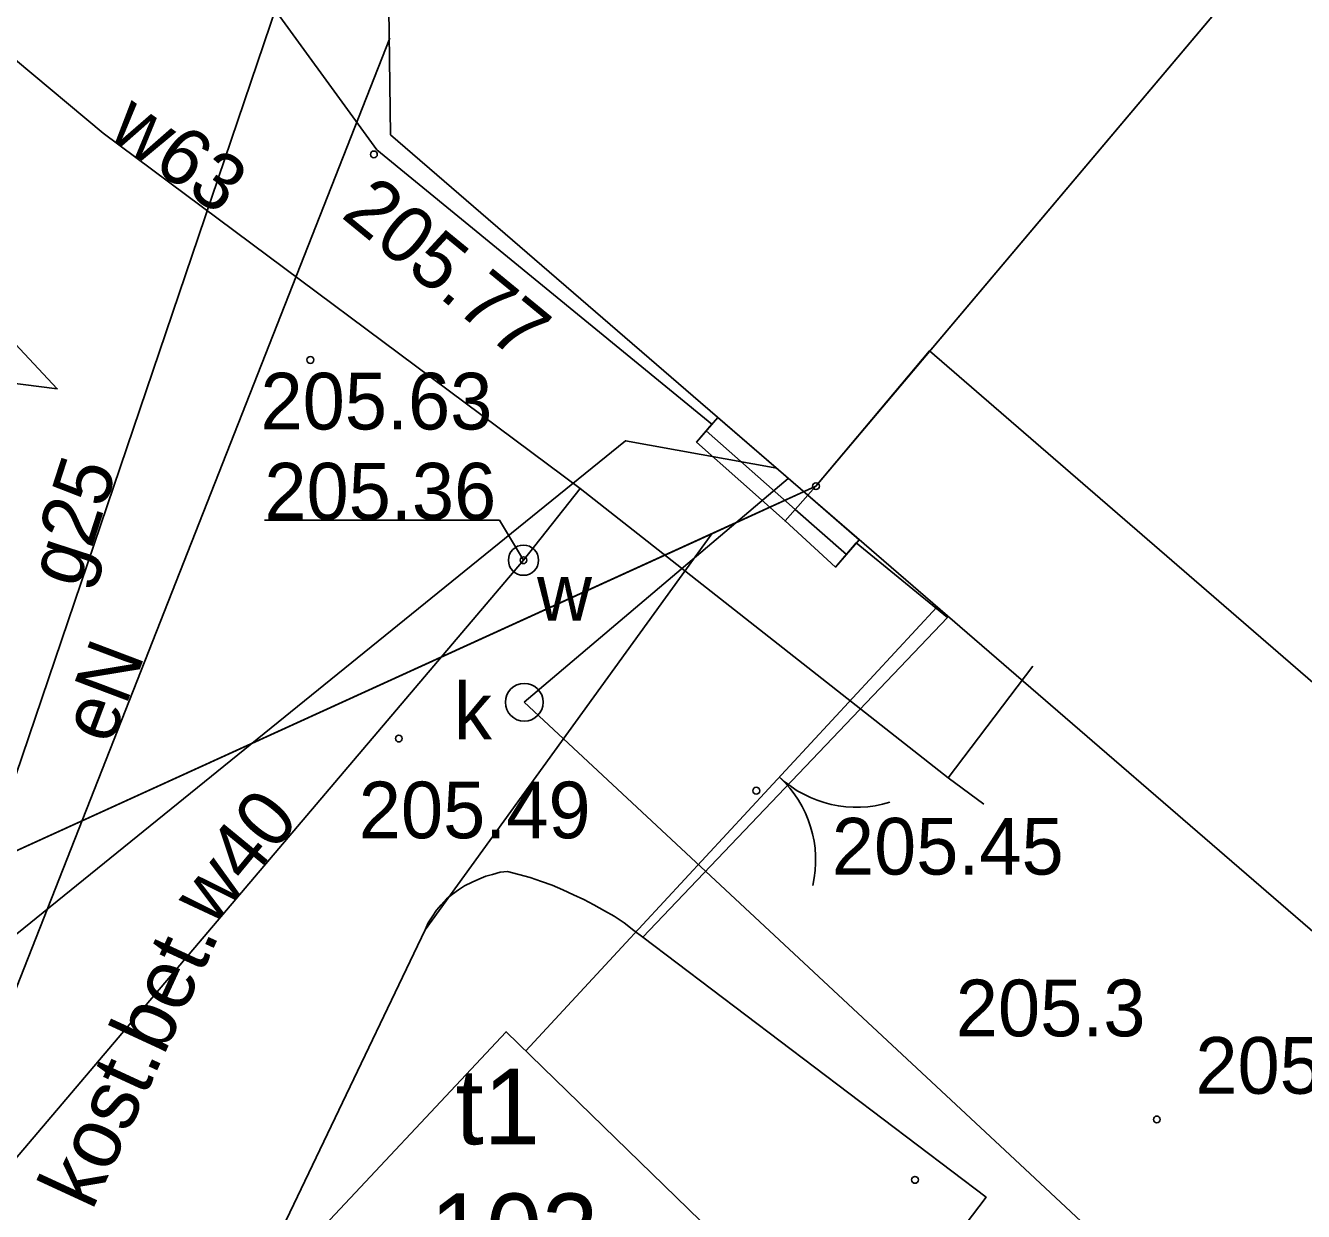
# Model space of a CAD drawing. Extents: x 6512606 to 6513006, y 6022524 to 6022728.
# Drawn here: x 6512766.96 to 6512783.87, y 6022649.64 to 6022665.33 of the extents above; entities that cross this region are included whole.
import ezdxf

# ---------------------------------------------------------------- set-up
doc = ezdxf.new("R2010")
doc.units = 0
for name, color, linetype in [('203-punkt graniczny', 7, 'Continuous'), ('217-kontur klasyfikacyjny', 7, 'Continuous'), ('218-kontur użytku gruntowego', 7, 'Continuous'), ('219-działka ewidencyjna', 7, 'Continuous'), ('312-budynek ewidencyjny', 7, 'Continuous'), ('312-oznaczenie budynku ewidencyjnego', 7, 'Continuous'), ('312-oznaczenie budynku ewidencyjnego-Atr117', 7, 'Continuous'), ('320-blok - kondygnacja nadziemna', 7, 'Continuous'), ('352-schody', 7, 'Continuous'), ('4', 7, 'Continuous'), ('433-Chodnik', 7, 'Continuous'), ('brama', 7, 'Continuous'), ('chodnik', 7, 'Continuous'), ('chodnik (powierzchnia)', 7, 'Continuous'), ('Default', 7, 'Continuous'), ('obszar utwardzony', 7, 'Continuous'), ('ogrodzenie trwałe', 7, 'Continuous'), ('pikieta naturalna', 7, 'Continuous'), ('pikieta naturalna-Atr2', 7, 'Continuous'), ('pikieta sztuczna', 7, 'Continuous'), ('pikieta sztuczna-Atr2', 7, 'Continuous'), ('przewód elektroenergetyczny (linia)', 7, 'Continuous'), ('przewód elektroenergetyczny (linia)-Atr1', 7, 'Continuous'), ('przewód gazowy (linia)', 7, 'Continuous'), ('przewód gazowy (linia)-Atr1', 7, 'Continuous'), ('przewód kanalizacyjny (linia)', 7, 'Continuous'), ('przewód wodociągowy (linia)', 7, 'Continuous'), ('przewód wodociągowy (linia)-Atr1', 7, 'Continuous'), ('punkt o określonej wysokości (sieć wodociągowa)', 7, 'Continuous'), ('punkt o określonej wysokości (sieć wodociągowa)-Atr2', 7, 'Continuous'), ('właz okrągły - siec kanalizacyjna (punkt)', 7, 'Continuous'), ('właz okrągły - siec kanalizacyjna (punkt)-Atr17', 7, 'Continuous'), ('zasuwa - siec wodociągowa (punkt)', 7, 'Continuous'), ('zasuwa - siec wodociągowa (punkt)-Atr17', 7, 'Continuous')]:
    doc.layers.add(name, color=color, linetype=linetype)

# ---------------------------------------------------------------- blocks, each defined once
blk = doc.blocks.new('203')
at = {"layer": 'Default'}
blk.add_circle((0, 0), 0.45, dxfattribs=at)
blk = doc.blocks.new('US22')
at = {"layer": 'Default'}
blk.add_circle((0, 0), 2.5, dxfattribs=at)
blk = doc.blocks.new('US25')
at = {"layer": 'Default'}
blk.add_circle((0, 0), 2, dxfattribs=at)
blk = doc.blocks.new('PW01')
at = {"layer": 'Default'}
blk.add_circle((0, 0), 0.45, dxfattribs=at)
blk = doc.blocks.new('OK02')
at = {"layer": 'Default'}
for centre, start, end in [((-15, 0), 0, 60), ((15, 0), 120, 180)]:
    blk.add_arc(centre, 15, start, end, dxfattribs=at)

msp = doc.modelspace()

# ---------------------------------------------------------------- linework, layer by layer
at = {"layer": '217-kontur klasyfikacyjny'}
for points in [[(6512786.09, 6022669.52), (6512777.42, 6022659.24)], [(6512777.42, 6022659.24), (6512776.04, 6022658.61)], [(6512776.04, 6022658.61), (6512772.25, 6022653.37)], [(6512772.25, 6022653.37), (6512764.49, 6022637.17)]]:
    msp.add_lwpolyline(points, dxfattribs=at)
at = {"layer": '218-kontur użytku gruntowego'}
for points in [[(6512786.09, 6022669.52), (6512777.42, 6022659.24)], [(6512777.42, 6022659.24), (6512786.09, 6022669.52)], [(6512762.17, 6022652.29), (6512777.42, 6022659.24)], [(6512777.42, 6022659.24), (6512776.04, 6022658.61)], [(6512776.04, 6022658.61), (6512762.17, 6022652.29)], [(6512776.04, 6022658.61), (6512772.25, 6022653.37)], [(6512772.25, 6022653.37), (6512776.04, 6022658.61)], [(6512772.25, 6022653.37), (6512764.49, 6022637.17)], [(6512764.49, 6022637.17), (6512772.25, 6022653.37)]]:
    msp.add_lwpolyline(points, dxfattribs=at)
at = {"layer": '219-działka ewidencyjna'}
for points in [[(6512777.42, 6022659.24), (6512790.49, 6022674.74)], [(6512777.42, 6022659.24), (6512762.17, 6022652.29)]]:
    msp.add_lwpolyline(points, dxfattribs=at)
at = {"layer": '312-budynek ewidencyjny'}
for points in [[(6512779.23, 6022661.39), (6512786.09, 6022669.52)], [(6512786.09, 6022669.52), (6512779.23, 6022661.39)], [(6512771.79, 6022663.89), (6512771.75, 6022666.89)], [(6512777.31, 6022659.12), (6512771.79, 6022663.89)], [(6512779.23, 6022661.39), (6512777.42, 6022659.24), (6512777.31, 6022659.12)], [(6512779.23, 6022661.39), (6512777.42, 6022659.24)], [(6512785.97, 6022651.64), (6512777.31, 6022659.12)]]:
    msp.add_lwpolyline(points, dxfattribs=at)
msp.add_lwpolyline([(6512770.59, 6022649.11), (6512773.32, 6022652.02), (6512775.89, 6022649.52), (6512773.2, 6022646.66)], close=True, dxfattribs=at)
at = {"layer": '320-blok - kondygnacja nadziemna'}
msp.add_lwpolyline([(6512787.51, 6022651.8), (6512788.38, 6022652.85), (6512778.92, 6022661.03), (6512777.42, 6022659.24), (6512777.31, 6022659.12), (6512785.97, 6022651.64)], close=True, dxfattribs=at)
at = {"layer": '352-schody'}
for points in [[(6512776.12, 6022660.15), (6512777.31, 6022659.12), (6512777.01, 6022658.78), (6512775.84, 6022659.82)], [(6512776.12, 6022660.15), (6512777.31, 6022659.12), (6512777.01, 6022658.78), (6512775.84, 6022659.82)], [(6512777.31, 6022659.12), (6512777.99, 6022658.53), (6512777.68, 6022658.17), (6512777.01, 6022658.78)], [(6512777.31, 6022659.12), (6512777.99, 6022658.53), (6512777.68, 6022658.17), (6512777.01, 6022658.78)]]:
    msp.add_lwpolyline(points, close=True, dxfattribs=at)
for points in [[(6512775.968, 6022659.971), (6512777.145, 6022658.933)], [(6512777.145, 6022658.933), (6512777.822, 6022658.335)]]:
    msp.add_lwpolyline(points, dxfattribs=at)
at = {"layer": '4'}
for points in [[(6512777.42, 6022659.24), (6512790.49, 6022674.74)], [(6512777.42, 6022659.24), (6512762.17, 6022652.29)]]:
    msp.add_lwpolyline(points, dxfattribs=at)
at = {"layer": 'brama'}
msp.add_lwpolyline([(6512779.02, 6022657.64), (6512774.85, 6022653.14)], dxfattribs=at)
at = {"layer": 'chodnik'}
msp.add_lwpolyline([(6512764.49, 6022637.17), (6512772.25, 6022653.37), (6512772.29, 6022653.46), (6512772.34, 6022653.54), (6512772.4, 6022653.63), (6512772.46, 6022653.7), (6512772.53, 6022653.78), (6512772.61, 6022653.84), (6512772.69, 6022653.9), (6512772.77, 6022653.95), (6512772.87, 6022654), (6512772.96, 6022654.04), (6512773.05, 6022654.08), (6512773.14, 6022654.1), (6512773.24, 6022654.13), (6512773.34, 6022654.14), (6512773.49, 6022654.1), (6512773.64, 6022654.06), (6512773.79, 6022654.01), (6512773.93, 6022653.96), (6512774.07, 6022653.9), (6512774.21, 6022653.83), (6512774.35, 6022653.77), (6512774.48, 6022653.7), (6512774.62, 6022653.62), (6512774.75, 6022653.55), (6512774.88, 6022653.46), (6512775.01, 6022653.36), (6512775.13, 6022653.27), (6512779.16, 6022657.5), (6512777.95, 6022658.49), (6512777.68, 6022658.17), (6512777.01, 6022658.78), (6512775.84, 6022659.82), (6512776.04, 6022660.06), (6512771.61, 6022663.69), (6512768.44, 6022668.05)], dxfattribs=at)
at = {"layer": 'chodnik (powierzchnia)'}
msp.add_lwpolyline([(6512762.98, 6022661.09), (6512767.38, 6022660.53), (6512765.47, 6022662.57), (6512765.23, 6022662.76), (6512764.98, 6022662.95), (6512764.72, 6022663.13), (6512764.45, 6022663.28), (6512764.18, 6022663.44), (6512763.9, 6022663.57), (6512763.61, 6022663.7), (6512763.32, 6022663.81), (6512763.02, 6022663.91), (6512762.72, 6022664), (6512762.41, 6022664.06), (6512762.11, 6022664.13), (6512761.8, 6022664.17), (6512761.49, 6022664.19), (6512761.68, 6022661.21)], close=True, dxfattribs=at)
at = {"layer": 'obszar utwardzony'}
msp.add_lwpolyline([(6512775.13, 6022653.27), (6512779.67, 6022649.83), (6512778.13, 6022647.8), (6512787.16, 6022640.57), (6512783.02, 6022635.41), (6512782.63, 6022634.93), (6512787.3, 6022631.38), (6512783.18, 6022625.97), (6512782.4, 6022624.88), (6512782.6, 6022624.74), (6512781.28, 6022622.94), (6512787.17, 6022619.72)], dxfattribs=at)
at = {"layer": 'ogrodzenie trwałe'}
msp.add_lwpolyline([(6512773.58, 6022651.77), (6512774.85, 6022653.14)], dxfattribs=at)
at = {"layer": 'przewód elektroenergetyczny (linia)'}
msp.add_lwpolyline([(6512759.34, 6022638.24), (6512761.23, 6022638.35), (6512771.78, 6022665.17)], dxfattribs=at)
at = {"layer": 'przewód gazowy (linia)'}
msp.add_lwpolyline([(6512759.32, 6022643.31), (6512762.68, 6022643.19), (6512770.72, 6022666.88)], dxfattribs=at)
at = {"layer": 'przewód kanalizacyjny (linia)'}
for points in [[(6512761.18, 6022648.73), (6512774.9, 6022659.84), (6512776.9, 6022659.48)], [(6512773.56, 6022656.38), (6512777.05, 6022659.34)], [(6512773.56, 6022656.38), (6512780.05, 6022650.33)], [(6512780.05, 6022650.33), (6512790.7, 6022640.38)]]:
    msp.add_lwpolyline(points, dxfattribs=at)
at = {"layer": 'przewód wodociągowy (linia)'}
for points in [[(6512779.64, 6022655.03), (6512779.17, 6022655.38), (6512774.3, 6022659.21), (6512767.99, 6022663.91), (6512766.83, 6022664.88), (6512766.4, 6022664.7), (6512766.07, 6022664.57)], [(6512759.39, 6022645.33), (6512762.57, 6022645.33), (6512773.55, 6022658.26), (6512774.3, 6022659.21)], [(6512780.29, 6022656.86), (6512779.17, 6022655.38)]]:
    msp.add_lwpolyline(points, dxfattribs=at)
at = {"layer": 'punkt o określonej wysokości (sieć wodociągowa)-Atr2'}
msp.add_lwpolyline([(6512773.55, 6022658.26), (6512773.23, 6022658.79), (6512770.121, 6022658.79)], dxfattribs=at)

# ---------------------------------------------------------------- block references
at = {"layer": '203-punkt graniczny', "xscale": 0.1, "yscale": 0.10000000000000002}
msp.add_blockref('203', (6512777.42, 6022659.24), dxfattribs=at)
at = {"layer": 'brama', "xscale": 0.10000000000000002, "yscale": 0.1, "rotation": -132.82}
msp.add_blockref('OK02', (6512776.935, 6022655.39), dxfattribs=at)
at = {"layer": 'pikieta naturalna', "xscale": 0.1, "yscale": 0.10000000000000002}
for p in [(6512781.93, 6022650.86), (6512778.73, 6022650.06)]:
    msp.add_blockref('PW01', p, dxfattribs=at)
at = {"layer": 'pikieta sztuczna', "xscale": 0.1, "yscale": 0.10000000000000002}
for p in [(6512771.57, 6022663.63), (6512770.73, 6022660.91), (6512771.9, 6022655.9), (6512776.63, 6022655.21)]:
    msp.add_blockref('PW01', p, dxfattribs=at)
at = {"layer": 'punkt o określonej wysokości (sieć wodociągowa)', "xscale": 0.10000000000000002, "yscale": 0.1, "rotation": 141.34}
msp.add_blockref('PW01', (6512773.55, 6022658.26), dxfattribs=at)
at = {"layer": 'właz okrągły - siec kanalizacyjna (punkt)', "xscale": 0.1, "yscale": 0.10000000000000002}
msp.add_blockref('US22', (6512773.56, 6022656.38), dxfattribs=at)
at = {"layer": 'zasuwa - siec wodociągowa (punkt)', "xscale": 0.10000000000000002, "yscale": 0.1, "rotation": 141.34}
msp.add_blockref('US25', (6512773.55, 6022658.26), dxfattribs=at)

# ---------------------------------------------------------------- texts
at = {"layer": '312-oznaczenie budynku ewidencyjnego'}
msp.add_text('103', height=1, dxfattribs=at).set_placement((6512772.31, 6022648.88))
at = {"layer": '312-oznaczenie budynku ewidencyjnego-Atr117'}
msp.add_text('t1', height=1, dxfattribs=at).set_placement((6512772.65, 6022650.53))
at = {"layer": '433-Chodnik'}
msp.add_text('kost.bet.', height=0.8, rotation=65.218, dxfattribs=at).set_placement((6512767.84, 6022649.64))
at = {"layer": 'pikieta naturalna-Atr2'}
for s, p in [('205.3', (6512779.27, 6022651.96)), ('205.1', (6512782.44, 6022651.2))]:
    msp.add_text(s, height=0.75, dxfattribs=at).set_placement(p)
at = {"layer": 'pikieta sztuczna-Atr2'}
msp.add_text('205.77', height=0.75, rotation=320.653, dxfattribs=at).set_placement((6512771.12, 6022662.81))
for s, p in [('205.63', (6512770.07, 6022659.99)), ('205.49', (6512771.37, 6022654.58)), ('205.45', (6512777.63, 6022654.1))]:
    msp.add_text(s, height=0.75, dxfattribs=at).set_placement(p)
at = {"layer": 'przewód elektroenergetyczny (linia)-Atr1'}
msp.add_text('eN', height=0.75, rotation=69.314, dxfattribs=at).set_placement((6512768.09, 6022655.8))
at = {"layer": 'przewód gazowy (linia)-Atr1'}
msp.add_text('g25', height=0.75, rotation=72.065, dxfattribs=at).set_placement((6512767.66, 6022657.87))
at = {"layer": 'przewód wodociągowy (linia)-Atr1'}
for s, rotation, p in [('w63', 324.528, (6512768.03, 6022663.88)), ('w40', 50.502, (6512769.43, 6022653.4))]:
    msp.add_text(s, height=0.75, rotation=rotation, dxfattribs=at).set_placement(p)
at = {"layer": 'punkt o określonej wysokości (sieć wodociągowa)-Atr2'}
msp.add_text('205.36', height=0.75, dxfattribs=at).set_placement((6512770.121, 6022658.798))
at = {"layer": 'właz okrągły - siec kanalizacyjna (punkt)-Atr17'}
msp.add_text('k', height=0.75, dxfattribs=at).set_placement((6512772.63, 6022655.89))
at = {"layer": 'zasuwa - siec wodociągowa (punkt)-Atr17'}
msp.add_text('w', height=0.75, dxfattribs=at).set_placement((6512773.73, 6022657.46))

doc.saveas('drawing.dxf')
